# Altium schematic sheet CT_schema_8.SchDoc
size 287 x 160 mm
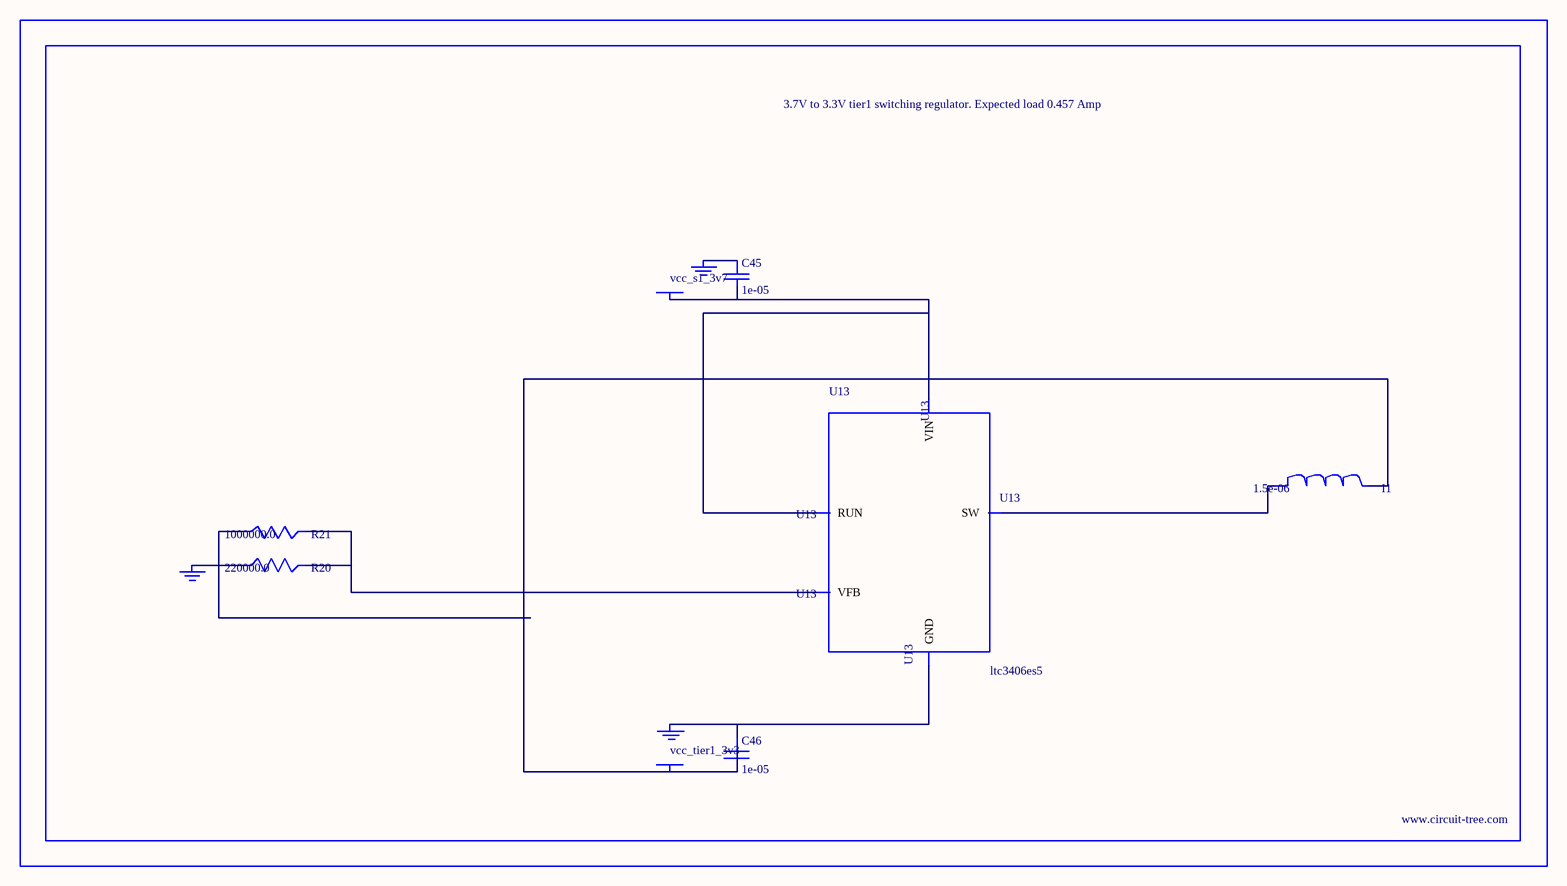
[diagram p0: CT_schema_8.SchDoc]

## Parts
BORDER7  (no value)
C45  1e-05  [C0805]
C46  1e-05  [C0805]
GND_INSTANCE_7_0  (no value)
GND_INSTANCE_7_1  (no value)
GND_INSTANCE_7_2  (no value)
I1  1.5e-06  [L0806]
POWER_INSTANCE_7_0  vcc_tier1_3v3
POWER_INSTANCE_7_1  vcc_s1_3v7
R20  220000.0  [R0603]
R21  1000000.0  [R0603]
U13  ltc3406es5  [TSOT-23-5]

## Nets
NetC45_1: C45.1 GND_INSTANCE_7_1.0(GND)
NetC45_2: C45.2 POWER_INSTANCE_7_1.0(PWR) U13.1(RUN) U13.4(VIN)
NetC46_1: C46.1 GND_INSTANCE_7_0.0(GND) U13.2(GND)
NetC46_2: C46.2 I1.2 POWER_INSTANCE_7_0.0(PWR) R21.1
NetGND_INSTANCE_7_2_0: GND_INSTANCE_7_2.0(GND) R20.1
NetI1_1: I1.1 U13.3(SW)
NetR20_2: R20.2 R21.2 U13.5(VFB)

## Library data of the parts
BORDER7 = BORDER_PAGE7
C45 C46 = C0805C106K8RACTU
GND_INSTANCE_7_0-GND_INSTANCE_7_2 = GND
I1 = L0806C1R5MDWIT
POWER_INSTANCE_7_0 POWER_INSTANCE_7_1 = PWR
R20 = RC0603JR-07220KL
R21 = RC0603JR-071ML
